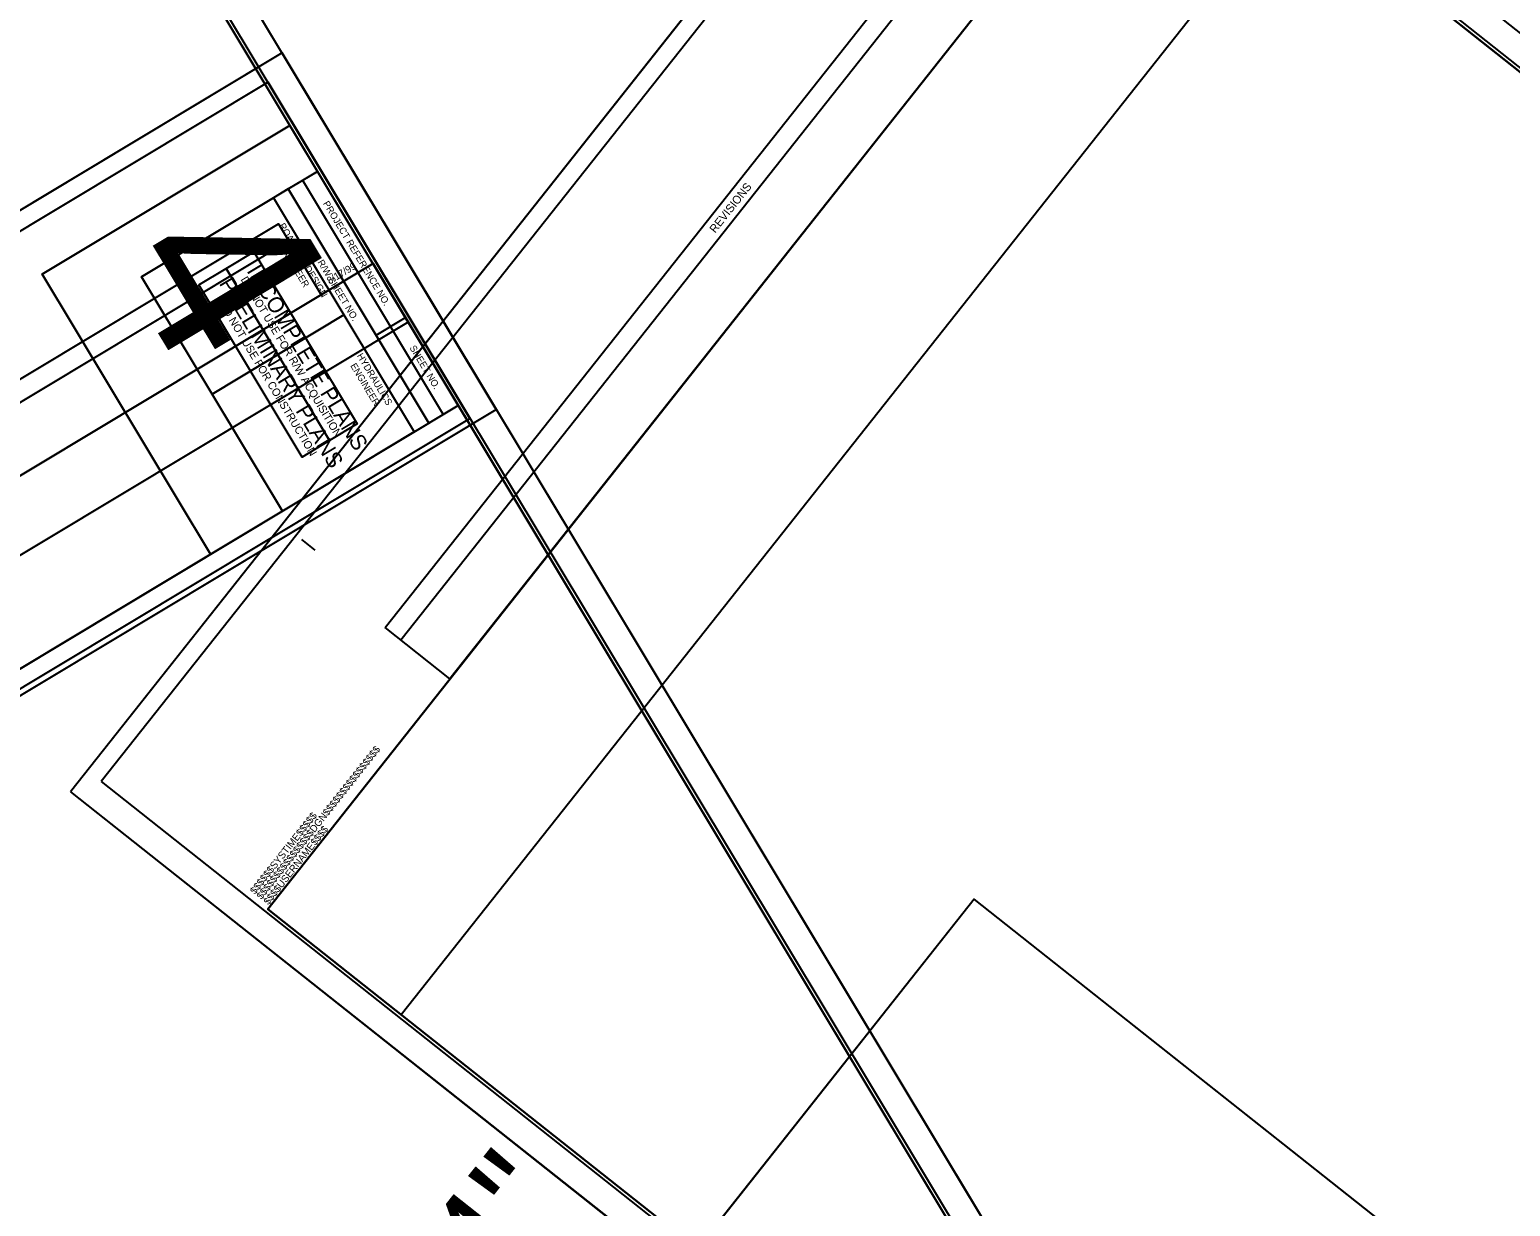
# Model space of a CAD drawing. Extents: x 1778994 to 1784559, y 810461 to 816654.
# Drawn here: x 1781058 to 1782142, y 814627 to 815489 of the extents above; entities that cross this region are included whole.
import ezdxf

# ---------------------------------------------------------------- set-up
doc = ezdxf.new("R2010")
doc.units = 0
for name, color, linetype in [('Sheet Block Revision CELL', 7, 'Continuous'), ('Sheet Clip Boundary CELL', 7, 'Continuous'), ('Sheet Cutting Line CELL', 7, 'Continuous'), ('Sheet Detail CELL', 7, 'Continuous'), ('Sheet Layout Plan Border', 7, 'Continuous'), ('Sheet Plan CELL', 7, 'Continuous'), ('Sheet Plan Layout CELL', 7, 'Continuous'), ('Sheet Plot Border Inside CELL', 7, 'Continuous'), ('Sheet Plot Border Outside CELL', 7, 'Continuous'), ('Sheet Sticker Incomplete CELL', 7, 'Continuous'), ('Sheet Sticker Preliminary CELL', 7, 'Continuous')]:
    doc.layers.add(name, color=color, linetype=linetype)

msp = doc.modelspace()

# ---------------------------------------------------------------- linework, layer by layer
at = {"layer": 'Sheet Block Revision CELL'}
for p, q in [((1781329.7, 815042.3), (1781820.5, 815662.2)), ((1780570.1, 814927.2), (1781247.8, 815334.5))]:
    msp.add_line(p, q, dxfattribs=at)
for points in [[(1781318.3, 815051.4), (1781809.1, 815671.2), (1781856.5, 815633.7), (1781365.8, 815013.8)], [(1780562.6, 814939.7), (1781240.3, 815346.9), (1781271.5, 815295), (1780593.8, 814887.8)]]:
    msp.add_lwpolyline(points, close=True, dxfattribs=at)
at = {"layer": 'Sheet Clip Boundary CELL'}
for points in [[(1781330.1, 814767.8), (1782427.7, 813898.8), (1782948.2, 814556.2), (1782799.8, 814673.7), (1782931.1, 814839.5), (1781981.8, 815591.1)], [(1780435.2, 814734.2), (1781156.3, 813534.2), (1781875, 813966.1), (1781777.6, 814128.3), (1781958.8, 814237.2), (1781335.3, 815275)]]:
    msp.add_lwpolyline(points, close=True, dxfattribs=at)
at = {"layer": 'Sheet Cutting Line CELL'}
for p, q in [((1781399.7, 815210.9), (1780532.7, 816653.9)), ((1781767.5, 815789.4), (1781087.8, 814930.9)), ((1781243, 815472.2), (1780304.4, 814908.2)), ((1782110.1, 814029.1), (1781243, 815472.2)), ((1781087.8, 814930.9), (1782407.7, 813885.9)), ((1781749.7, 814852.4), (1780384.1, 813127.6)), ((1784390.3, 812761.8), (1781749.7, 814852.4))]:
    msp.add_line(p, q, dxfattribs=at)
at = {"layer": 'Sheet Layout Plan Border'}
for points in [[(1781330.1, 814767.8), (1782427.7, 813898.8), (1782948.2, 814556.2), (1782799.8, 814673.7), (1782931.1, 814839.5), (1781981.8, 815591.1)], [(1780435.2, 814734.2), (1781156.3, 813534.2), (1781875, 813966.1), (1781777.6, 814128.3), (1781958.8, 814237.2), (1781335.3, 815275)]]:
    msp.add_lwpolyline(points, close=True, dxfattribs=at)
at = {"layer": 'Sheet Plan CELL'}
for p, q in [((1781257.9, 815378.9), (1781360.9, 815207.4)), ((1781247.2, 815372.5), (1781236.5, 815366)), ((1781247.2, 815372.5), (1781350.2, 815201)), ((1781247.2, 815372.5), (1781350.2, 815201)), ((1781309.5, 815317.9), (1781309.5, 815317.9)), ((1781288, 815280.3), (1781191.6, 815222.3)), ((1781333, 815278.2), (1781311.6, 815265.3)), ((1781257.1, 815115.8), (1781266.9, 815108)), ((1781232.3, 814845.2), (1781232.3, 814845.2))]:
    msp.add_line(p, q, dxfattribs=at)
for points in [[(1781371.7, 815213.9), (1780599.1, 816499.7), (1779699.1, 815958.9), (1780471.7, 814673.1)], [(1779699.1, 815958.9), (1780599.1, 816499.7), (1781268.7, 815385.4), (1781140, 815308.1), (1781243.1, 815136.6), (1780471.7, 814673.1)], [(1783060.1, 814737.4), (1781884.1, 815668.5), (1781232.3, 814845.2), (1782408.4, 813914.1)], [(1781232.3, 814845.2), (1781884, 815668.5), (1782903.3, 814861.6), (1782810.1, 814743.9), (1782967, 814619.7), (1782408.4, 813914.1)], [(1781268.7, 815385.4), (1781371.7, 815213.9), (1781350.2, 815201), (1781247.2, 815372.5)], [(1781236.5, 815366), (1781288, 815280.3), (1781191.6, 815222.3), (1781140, 815308.1)], [(1782082.1, 814032.1), (1781309.5, 815317.9), (1780409.5, 814777.1), (1781182, 813491.3)], [(1780409.5, 814777.1), (1781309.5, 815317.9), (1781979, 814203.6), (1781850.4, 814126.3), (1781953.4, 813954.8), (1781182, 813491.3)], [(1781288, 815280.3), (1781339.5, 815194.6), (1781243.1, 815136.6), (1781191.6, 815222.3)]]:
    msp.add_lwpolyline(points, close=True, dxfattribs=at)
at = {"layer": 'Sheet Plan Layout CELL'}
for points in [[(1780599.1, 816499.7), (1779699.1, 815958.9), (1780471.7, 814673.1), (1781190.4, 815105), (1781067.2, 815310.1), (1781248.5, 815419)], [(1781884, 815668.5), (1781232.3, 814845.2), (1782408.3, 813914.1), (1782928.8, 814571.6), (1782741.3, 814720.1), (1782872.5, 814885.9)], [(1781067.2, 815310.1), (1781190.4, 815105), (1781371.7, 815213.9), (1781248.5, 815419)], [(1781309.5, 815317.9), (1780409.5, 814777.1), (1781182, 813491.4), (1781900.8, 813923.2), (1781777.6, 814128.3), (1781958.8, 814237.2)]]:
    msp.add_lwpolyline(points, close=True, dxfattribs=at)
at = {"layer": 'Sheet Plot Border Inside CELL'}
for points in [[(1779617.9, 816089.1), (1780476, 814661.1), (1781380.3, 815204.5), (1780522.2, 816632.5)], [(1781110.4, 814938.5), (1782416.6, 813904.4), (1783071.5, 814731.6), (1781765.3, 815765.7)], [(1780328.3, 814907.4), (1781186.3, 813479.3), (1782090.6, 814022.7), (1781232.6, 815450.7)]]:
    msp.add_lwpolyline(points, close=True, dxfattribs=at)
at = {"layer": 'Sheet Plot Border Outside CELL'}
for points in [[(1779594.1, 816090), (1780461.1, 814646.9), (1781399.7, 815210.9), (1780532.7, 816653.9)], [(1781087.8, 814930.9), (1782407.7, 813885.9), (1783087.4, 814744.4), (1781767.5, 815789.4)], [(1780304.4, 814908.2), (1781171.5, 813465.2), (1782110.1, 814029.1), (1781243, 815472.2)], [(1784390.3, 812761.8), (1781749.7, 814852.4), (1780384.1, 813127.6), (1783024.7, 811037)]]:
    msp.add_lwpolyline(points, close=True, dxfattribs=at)
at = {"layer": 'Sheet Sticker Incomplete CELL'}
msp.add_lwpolyline([(1781201.9, 815314.3), (1781222.1, 815326.4), (1781297.8, 815200.4), (1781277.6, 815188.3)], close=True, dxfattribs=at)
at = {"layer": 'Sheet Sticker Preliminary CELL'}
msp.add_lwpolyline([(1781181.8, 815302.2), (1781201.9, 815314.3), (1781277.6, 815188.3), (1781257.5, 815176.2)], close=True, dxfattribs=at)

# ---------------------------------------------------------------- texts
at = {"layer": 'Sheet Block Revision CELL'}
msp.add_text('REVISIONS', height=6, rotation=51.6309, dxfattribs=at).set_placement((1781560, 815339.8))
at = {"layer": 'Sheet Detail CELL'}
msp.add_text('TO PLOT FULL SIZE 62"X34"', height=75, rotation=51.6309, dxfattribs=at).set_placement((1780624.2, 813575.5))
at = {"layer": 'Sheet Plan CELL'}
for s, height, rotation, p in [('PROJECT REFERENCE NO.', 5, 301, (1781272.6, 815361.9)), ('ROADWAY DESIGN', 5, 301, (1781240.2, 815345.7)), ('ENGINEER', 5, 301, (1781240.9, 815329.8)), ('R/W SHEET NO.', 5, 301, (1781268.6, 815318.9)), ('8/17/99', 5.25, 31, (1781277.6, 815302.5)), ('HYDRAULICS', 5, 301, (1781297.4, 815250.4)), ('SHEET NO.', 5, 301, (1781336, 815256.2)), ('ENGINEER', 5, 301, (1781292.6, 815243.1)), ('$$$$$$$$$$$$$$$$DGN$$$$$$$$$$$$$$$$', 5.25, 51.6309, (1781227.8, 814851.8)), ('$$$$$$SYSTIME$$$$$', 5.25, 51.6309, (1781223, 814855.6)), ('$$$$USERNAME$$$$', 5.25, 51.6309, (1781232.9, 814847.8))]:
    msp.add_text(s, height=height, rotation=rotation, dxfattribs=at).set_placement(p)
at = {"layer": 'Sheet Plan Layout CELL'}
msp.add_text('4 ', height=131.25, rotation=301, dxfattribs=at).set_placement((1781120.6, 815319.1))
at = {"layer": 'Sheet Sticker Incomplete CELL'}
for s, height, p in [('INCOMPLETE PLANS', 11.52, (1781216.6, 815312.6)), ('DO NOT USE FOR R/W ACQUISITION', 5.76, (1781212.3, 815306.3))]:
    msp.add_text(s, height=height, rotation=301, dxfattribs=at).set_placement(p)
at = {"layer": 'Sheet Sticker Preliminary CELL'}
for s, height, p in [('PRELIMINARY PLANS', 11.52, (1781196.4, 815303.4)), ('DO NOT USE FOR CONSTRUCTION', 5.76, (1781196.5, 815288.2))]:
    msp.add_text(s, height=height, rotation=301, dxfattribs=at).set_placement(p)

doc.saveas('drawing.dxf')
